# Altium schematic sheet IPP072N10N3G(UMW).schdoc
size 127 x 101 mm
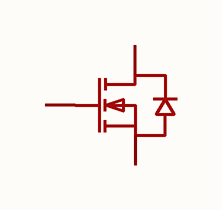
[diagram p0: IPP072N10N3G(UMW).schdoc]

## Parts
Q?  ipp072n10n3g(umw)  [TO-220-3_L9.9-W4.5-P2.54-L]  (value not drawn)

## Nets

Not connected (* = marked no-connect by the designer): Q? 1(G) 2(D) 3(S)

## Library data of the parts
Q? = ipp072n10n3g(umw): 数量:1个N沟道;漏源电压(Vdss):100V;连续漏极电流(Id):80A;导通电阻(RDS(on)):6.2mΩ@10V;耗散功率(Pd):150W;阈值电压(Vgs(th)):2.7V;; Manufacturer: UMW(友台半导体); AddInBom: yes; ModelId: 61b625ab855b4726be53be943295af7a; ModelTransform: 389.763,177.165,0,0,0,0,0,6.693,-118.11; Number: 1个N沟道; Drain to Source Voltage: 100V; Current - Continuous Drain(Id): 80A; Pd - Power Dissipation: 150W; Gate Threshold Voltage (Vgs(th)): 2.7V; Gate Charge(Qg): 68nC@10V; Input Capacitance(Ciss): 3.69nF; Type: N沟道; Output Capacitance(Coss): 646pF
